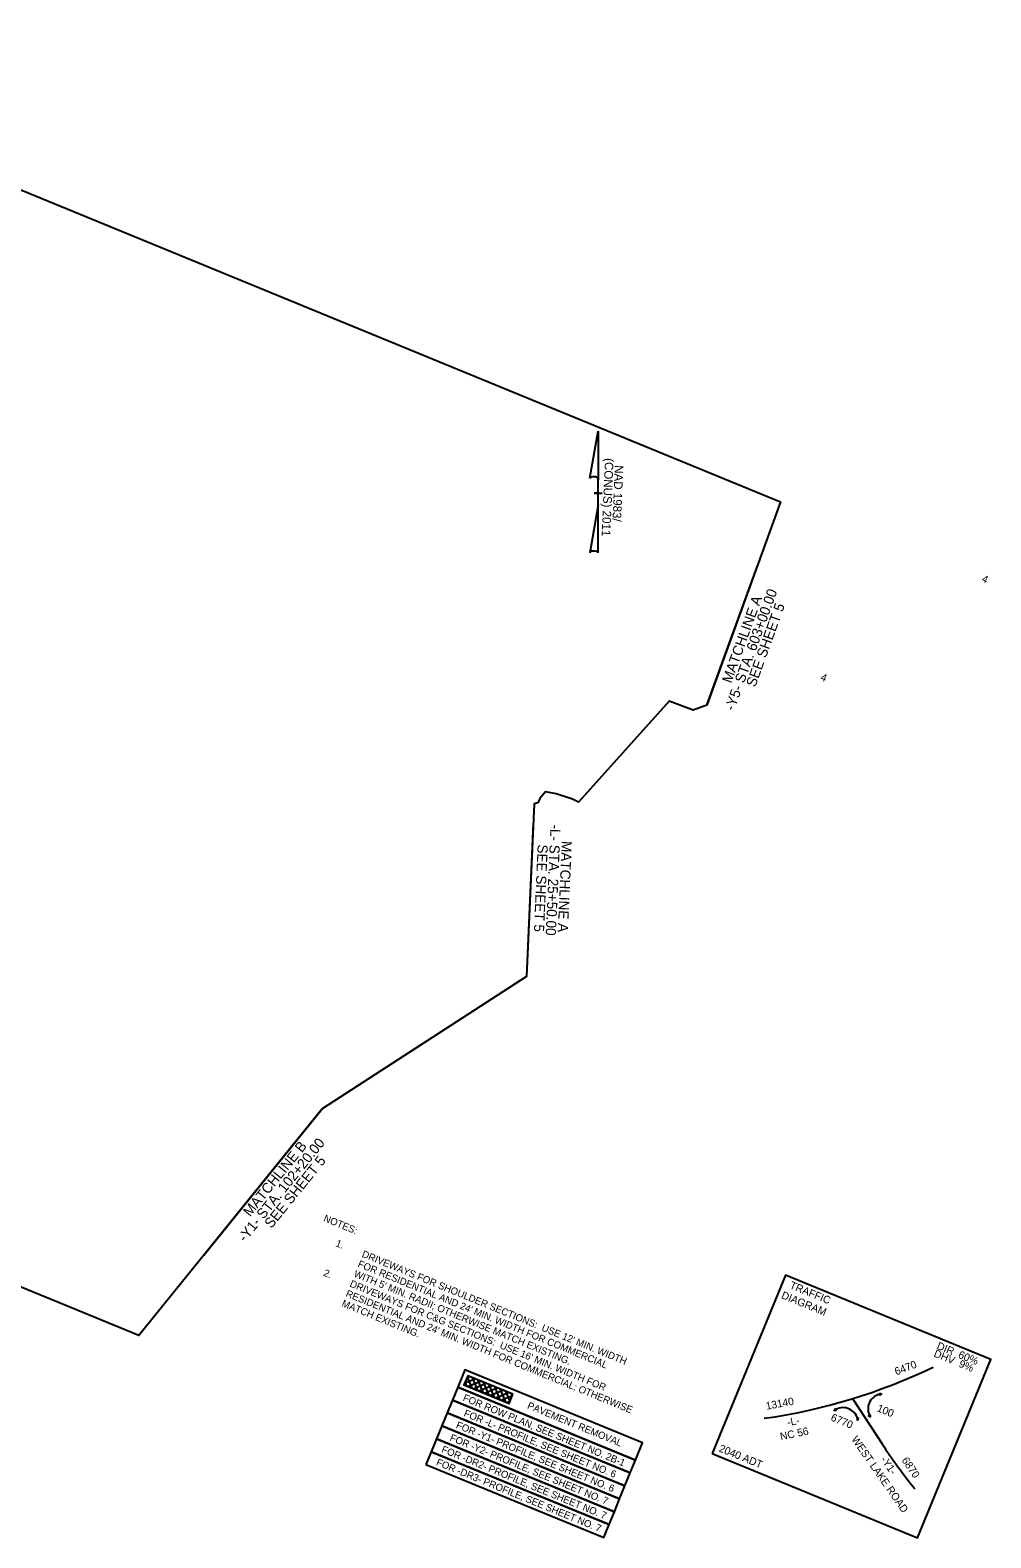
# Model space of a CAD drawing. Extents: x 2090211 to 2092104, y 863357 to 864842.
import ezdxf

# ---------------------------------------------------------------- set-up
doc = ezdxf.new("R2010")
doc.units = 0
for name, color, linetype in [('Matchline', 7, 'Continuous'), ('Matchline Text', 7, 'Continuous'), ('Prop DSN Text', 7, 'Continuous'), ('Prop Grid Mask', 7, 'Continuous'), ('Prop Hatching', 7, 'Continuous'), ('Prop Horizontal Alignment', 7, 'Continuous'), ('Prop North Arrow for Plan Sheets CELL', 7, 'Continuous'), ('Prop North Arrow NAD83 for Plan Sheets CELL', 7, 'Continuous'), ('Sheet Clip Boundary CELL', 7, 'Continuous'), ('Sheet Data Field CELL', 7, 'Continuous')]:
    doc.layers.add(name, color=color, linetype=linetype)

msp = doc.modelspace()

# ---------------------------------------------------------------- linework, layer by layer
at = {"layer": 'Matchline'}
for p, q in [((2091824.5, 864177.1), (2091873.9, 864313.4)), ((2091653.3, 864060.7), (2091646.7, 863909.8)), ((2091328.8, 863635.3), (2091445.4, 863779.5))]:
    msp.add_line(p, q, dxfattribs=at)
at = {"layer": 'Prop DSN Text'}
msp.add_lwpolyline([(2091829.8, 863439.9), (2092032.1, 863356.8), (2092104.3, 863532.5), (2091902, 863615.6)], close=True, dxfattribs=at)
for points in [[(2091994.7, 863499.3), (2091996.5, 863498.7), (2091995, 863497.4), (2091994.8, 863498.3), (2091994.7, 863499.3)], [(2091951, 863484.1), (2091950, 863482.4), (2091952, 863482.5), (2091951.5, 863483.3), (2091951, 863484.1)], [(2091972.1, 863474.3), (2091973.4, 863472.8), (2091973.9, 863474.7), (2091973, 863474.5), (2091972.1, 863474.3)], [(2091985.5, 863477.9), (2091985.5, 863475.9), (2091983.9, 863477), (2091984.7, 863477.4), (2091985.5, 863477.9)]]:
    msp.add_lwpolyline(points, dxfattribs=at)
for centre, start, end in [((2091998.3, 863483.8), 103.4441, 211.4789), ((2091958.6, 863470.1), 10.3766, 118.4114)]:
    msp.add_arc(centre, 15, start, end, dxfattribs=at)
at = {"layer": 'Prop Grid Mask'}
for points in [[(2091579, 863505.4), (2091754.2, 863433.4), (2091761.1, 863450.4), (2091586, 863522.3)], [(2091573.8, 863492.6), (2091749, 863420.7), (2091754.2, 863433.4), (2091579, 863505.4)], [(2091633.3, 863498.3), (2091588.9, 863516.5), (2091585.1, 863507.4), (2091629.6, 863489.2)], [(2091568.6, 863479.9), (2091743.7, 863408), (2091749, 863420.7), (2091573.8, 863492.6)], [(2091563.3, 863467.2), (2091738.5, 863395.2), (2091743.7, 863408), (2091568.6, 863479.9)], [(2091558.1, 863454.5), (2091733.3, 863382.5), (2091738.5, 863395.2), (2091563.3, 863467.2)], [(2091552.9, 863441.7), (2091728.1, 863369.8), (2091733.3, 863382.5), (2091558.1, 863454.5)], [(2091547.7, 863429), (2091722.8, 863357.1), (2091728.1, 863369.8), (2091552.9, 863441.7)]]:
    msp.add_lwpolyline(points, close=True, dxfattribs=at)
at = {"layer": 'Prop Hatching'}
for p, q in [((2091586, 863509.4), (2091596, 863513.6)), ((2091586.1, 863509.8), (2091587.5, 863506.5)), ((2091588.2, 863514.9), (2091590.5, 863515.9)), ((2091588.4, 863515.3), (2091593, 863504.2)), ((2091588.7, 863506), (2091601.5, 863511.3)), ((2091593.1, 863514.8), (2091598.5, 863501.9)), ((2091594.2, 863503.7), (2091607, 863509.1)), ((2091598.6, 863512.5), (2091604, 863499.7)), ((2091599.7, 863501.5), (2091612.5, 863506.8)), ((2091604.1, 863510.3), (2091609.5, 863497.4)), ((2091605.2, 863499.2), (2091618, 863504.6)), ((2091609.6, 863508), (2091615, 863495.2)), ((2091615.1, 863505.8), (2091620.5, 863492.9)), ((2091620.6, 863503.5), (2091626, 863490.7)), ((2091610.6, 863497), (2091623.5, 863502.3)), ((2091616.1, 863494.7), (2091629, 863500.1)), ((2091621.6, 863492.4), (2091632.8, 863497.1)), ((2091626.1, 863501.3), (2091630.4, 863491)), ((2091627.1, 863490.2), (2091630.6, 863491.6)), ((2091631.6, 863499), (2091632.6, 863496.5))]:
    msp.add_line(p, q, dxfattribs=at)
at = {"layer": 'Prop Horizontal Alignment'}
msp.add_line((2091968.1, 863494), (2091997.2, 863449.4), dxfattribs=at)
for centre, radius, start, end in [((2091802, 864034), 565, 278.0413, 295.7537), ((2092443.6, 863740.6), 533, 213.1208, 219.0168)]:
    msp.add_arc(centre, radius, start, end, dxfattribs=at)
at = {"layer": 'Prop North Arrow for Plan Sheets CELL'}
for p, q in [((2091709.1, 864400.7), (2091717.3, 864447.1)), ((2091717.3, 864447.1), (2091717.3, 864447.1)), ((2091717.3, 864447.1), (2091717.3, 864447.1)), ((2091717.3, 864447.1), (2091717.3, 864399.3)), ((2091717.3, 864374.5), (2091717.3, 864400.7)), ((2091717.3, 864399.3), (2091717.3, 864400.6)), ((2091716.9, 864386.1), (2091713.3, 864386.1)), ((2091713.3, 864386.1), (2091713.3, 864386.1)), ((2091713.4, 864386.1), (2091721.4, 864386.1)), ((2091717.3, 864374.5), (2091709, 864327.2)), ((2091717.4, 864327.4), (2091717.3, 864374.5))]:
    msp.add_line(p, q, dxfattribs=at)
for centre, start_param, end_param in [((2091713.2, 864400.2), 0.216388, 2.908219), ((2091713.2, 864327.1), 0.201328, 3.141593)]:
    msp.add_ellipse(centre, major_axis=(4.23, -0.03), ratio=0.461098, start_param=start_param, end_param=end_param, dxfattribs=at)
at = {"layer": 'Sheet Clip Boundary CELL'}
msp.add_lwpolyline([(2090600.1, 864440.2), (2090595.8, 864457.4), (2090708.6, 864727.1), (2090720, 864732.2), (2090765.2, 864842.2), (2091897, 864377.4), (2091824.5, 864177.1), (2091824.5, 864177.1), (2091824.5, 864177.1), (2091811.1, 864172.4), (2091787.3, 864181.2), (2091698.1, 864081.6), (2091692.1, 864084.4), (2091676, 864089.7), (2091665.5, 864091.7), (2091659.8, 864085.3), (2091657.8, 864080.8), (2091657.8, 864080.8), (2091654.2, 864080.1), (2091646.7, 863909.8), (2091445.4, 863779.5), (2091264.7, 863556), (2090385.3, 863917.2)], close=True, dxfattribs=at)

# ---------------------------------------------------------------- texts
at = {"layer": 'Matchline Text'}
for s, rotation, p in [('-Y5- STA. 603+00.00', 70.1116, (2091851.2, 864171)), ('MATCHLINE A', 70.1116, (2091848.5, 864198.2)), ('SEE SHEET 5', 70.1116, (2091872.2, 864194.4)), ('-L- STA. 25+50.00', 267.4725, (2091670.5, 864059.9)), ('SEE SHEET 5', 267.4725, (2091657.8, 864040.1)), ('MATCHLINE A', 267.4725, (2091681.5, 864043.5)), ('-Y1- STA. 102+20.00', 51.0406, (2091369.4, 863647.6)), ('MATCHLINE B', 51.0406, (2091374.4, 863672.6)), ('SEE SHEET 5', 51.0406, (2091395.4, 863661))]:
    msp.add_text(s, height=10, rotation=rotation, dxfattribs=at).set_placement(p)
at = {"layer": 'Prop DSN Text'}
for s, height, rotation, p in [('NOTES:', 7, 337.6724, (2091446.1, 863669)), ('1.', 7, 337.6724, (2091458, 863644.4)), ("DRIVEWAYS FOR SHOULDER SECTIONS:  USE 12' MIN. WIDTH", 7, 337.6724, (2091483.9, 863633.8)), ("FOR RESIDENTIAL AND 24' MIN. WIDTH FOR COMMERCIAL", 7, 337.6724, (2091479.9, 863624.1)), ('2.', 7, 337.6724, (2091446.1, 863615.3)), ("DRIVEWAYS FOR C&G SECTIONS:  USE 16' MIN. WIDTH FOR", 7, 337.6724, (2091472, 863604.6)), ("WITH 5' MIN. RADII; OTHERWISE MATCH EXISTING.", 7, 337.6724, (2091476, 863614.4)), ('TRAFFIC', 7.5, 337.6724, (2091905.4, 863602.9)), ("RESIDENTIAL AND 24' MIN. WIDTH FOR COMMERCIAL; OTHERWISE", 7, 337.6724, (2091468, 863594.9)), ('DIAGRAM', 7.5, 337.6724, (2091897.2, 863593.1)), ('MATCH EXISTING.', 7, 337.6724, (2091464, 863585.2)), ('DIR  60%', 7.5, 337.6724, (2092050.4, 863543.2)), ('DHV  9%', 7.5, 337.6724, (2092047.4, 863535.7)), ('6470', 7.5, 21.188, (2092011.2, 863516.8)), ('FOR ROW PLAN, SEE SHEET NO. 2B-1', 7, 337.6724, (2091583.5, 863492.2)), ('PAVEMENT REMOVAL', 7, 337.6724, (2091646.9, 863484.5)), ('13140', 7.5, 10.7595, (2091883.3, 863482.9)), ('FOR -L- PROFILE, SEE SHEET NO. 6', 7, 337.6724, (2091584.3, 863477)), ('-L-', 7.5, 11.6014, (2091904.4, 863466.8)), ('6770', 7.5, 337.6724, (2091945.9, 863472.7)), ('100', 7.5, 337.6724, (2091991.4, 863481.8)), ('FOR -Y2- PROFILE, SEE SHEET NO. 7', 7, 337.6724, (2091570.6, 863452.9)), ('FOR -Y1- PROFILE, SEE SHEET NO. 6', 7, 337.6724, (2091576.7, 863465.3)), ('NC 56', 7.5, 11.6014, (2091897.4, 863452.9)), ('FOR -DR2- PROFILE, SEE SHEET NO. 7', 7, 337.6724, (2091562.3, 863441.4)), ('2040 ADT', 7.5, 337.6724, (2091835.7, 863442.2)), ('WEST LAKE ROAD', 7.5, 304.8006, (2091966.5, 863453.9)), ('FOR -DR3- PROFILE, SEE SHEET NO. 7', 7, 337.6724, (2091557.1, 863428.7)), ('-Y1-', 7.5, 304.8006, (2091995.3, 863433.9)), ('6870', 7.5, 304.5006, (2092016, 863433.2))]:
    msp.add_text(s, height=height, rotation=rotation, dxfattribs=at).set_placement(p)
at = {"layer": 'Prop North Arrow NAD83 for Plan Sheets CELL'}
for s, p in [('(CONUS) 2011', (2091724.1, 864420.7)), ('NAD 1983/ ', (2091733.8, 864413.7))]:
    msp.add_text(s, height=8.5, rotation=267.5603, dxfattribs=at).set_placement(p)
at = {"layer": 'Sheet Data Field CELL'}
for p in [(2092094.6, 864299), (2091935.8, 864202.1)]:
    msp.add_text('4', height=7.5, rotation=337.6724, dxfattribs=at).set_placement(p)

doc.saveas('drawing.dxf')
